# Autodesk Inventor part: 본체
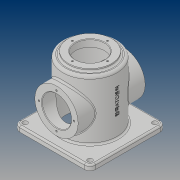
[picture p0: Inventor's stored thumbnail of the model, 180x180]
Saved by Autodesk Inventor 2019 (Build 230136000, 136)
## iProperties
Created: 2019-03
Part Number: 본체
Material: 일반
Document SubType Name: Modeling
Designer: PC312-03
Density: 1 g/cm^3
Appearance: 기본값
Author: PC312-03
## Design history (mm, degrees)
sketch "스케치1"
  geometry: C1 r 50 at (0, 0); 1 further point
  constraints: 1 centre point, 1 coincident
  dimensions: "d0" = 100 diameter of C1
extrude "돌출1" new body sketch "스케치1" distance "d1" = 120; taper "d2" = 0 deg
sketch "스케치2"
  geometry: C1 r 45 at (0, 0); 1 further point
  constraints: 1 centre point, 1 coincident
  dimensions: "d3" = 90 diameter of C1
extrude "돌출2" cut sketch "스케치2" distance "d4" = 112; taper "d5" = 0 deg
sketch "스케치3"
  geometry: L1 (-70, 70)-(70, 70); L2 (70, 70)-(70, -70); L3 (70, -70)-(-70, -70); L4 (-70, -70)-(-70, 70); L5 (-70, 70)-(70, -70); L6 (70, 70)-(-70, -70); C1 r 45 at (0, 0) reference; C2 r 50 at (0, 0) reference; 1 further point
  constraints: 12 end point, 2 midpoint, 2 parallel, 1 horizontal, 1 perpendicular
  dimensions: "d6" = 140 distance of L2.end L3.end; "d7" = 140 distance of L1.end L2.end
extrude "돌출3" join sketch "스케치3" distance "d8" = 10; taper "d9" = 0 deg
node "작업 평면1"
sketch "스케치4"
  geometry: C1 r 40 at (0, 60); 1 further point
  constraints: 1 centre point, 1 vertical alignment
  dimensions: "d11" = 80 diameter of C1; "d12" = 60 distance of point (0, 0) C1.centre
extrude "돌출4" join sketch "스케치4" stored distance "d13" = 10; taper "d14" = 0 deg
sketch "스케치5"
  geometry: C1 r 40 at (0, 0) reference; 2 further points
  constraints: 1 vertical alignment
  dimensions: "d15" = 32.5 distance of C1.centre point (0, 32.5)
hole "구멍1" sketch "스케치5" at (0, 32.5) diameter "d16" = 3.242; stored, may be unused: countersink angle "d20" = 90 deg, drill point angle "d22" = 118 deg; dims "d17" = 8, "d18" = 4, "d19" = 2, "d21" = 10
sketch "스케치6"
  geometry: C1 r 40 at (0, 0) reference; C2 r 27 at (0, 0); 1 further point
  constraints: 1 centre point, 1 coincident
  dimensions: "d26" = 54 diameter of C2
extrude "돌출5" cut sketch "스케치6" extent not by distance; stored distance "d27" = 10; taper "d28" = 0 deg
sketch "스케치7"
  geometry: C1 r 40 at (0, 0); 1 further point
  constraints: 1 centre point, 1 coincident
  dimensions: "d29" = 80 diameter of C1
extrude "돌출6" join sketch "스케치7" distance "d30" = 5; taper "d31" = 0 deg
sketch "스케치8"
  geometry: 2 further points
  constraints: 1 vertical alignment
  dimensions: "d32" = 32.5 distance of point (0, 0) point (0, 32.5)
hole "구멍2" sketch "스케치8" at (0, 32.5) diameter "d33" = 3.242; stored, may be unused: countersink angle "d37" = 90 deg, drill point angle "d39" = 118 deg; dims "d34" = 8, "d35" = 4, "d36" = 2, "d38" = 10
sketch "스케치9"
  geometry: C1 r 27 at (0, 0); 1 further point
  constraints: 1 centre point, 1 coincident
  dimensions: "d43" = 54 diameter of C1
extrude "돌출7" cut sketch "스케치9" extent not by distance; stored distance "d44" = 5; taper "d45" = 0 deg
fillet "모깎기1" dims "d46" = 10
sketch "스케치10"
  geometry: A1 r 10 centre (-60, -60) between (-70, -60) and (-60, -70) reference; A2 r 10 centre (60, -60) between (60, -70) and (70, -60) reference; A3 r 10 centre (60, 60) between (70, 60) and (60, 70) reference; A4 r 10 centre (-60, 60) between (-60, 70) and (-70, 60) reference; 5 further points
  constraints: 4 coincident
hole "구멍3" sketch "스케치10" at (-60, -60), (60, -60), (60, 60), (-60, 60) diameter "d47" = 9; stored, may be unused: countersink angle "d51" = 90 deg, drill point angle "d53" = 118 deg; dims "d48" = 8, "d49" = 4, "d50" = 2, "d52" = 10
fillet "모깎기2" dims "d54" = 5
fillet "모깎기3" dims "d55" = 3
fillet "모깎기4" dims "d56" = 3
fillet "모깎기5" dims "d57" = 3
chamfer "모따기1" distance "d58" = 1; stored, may be unused: second distance "d59" = 2, angle "d60" = 45 deg
node "작업 평면2"
sketch "스케치11"
  geometry: 2 further points
  constraints: 1 horizontal alignment, 1 other
  dimensions: "d62" = 70 distance of point (0, 0) point (70, 0)
feature "엠보싱1" sketch "스케치11" dims "d63" = 0.5, "d64" = 0
node "솔리드1"
pattern_circular "원형 패턴1" dims angle "d24" = 360 deg
mirror "미러1"
pattern_circular "원형 패턴2" dims angle "d41" = 360 deg
node "투영된 루프1"
other parameters: "d10" = 62, "d61" = 86.75
